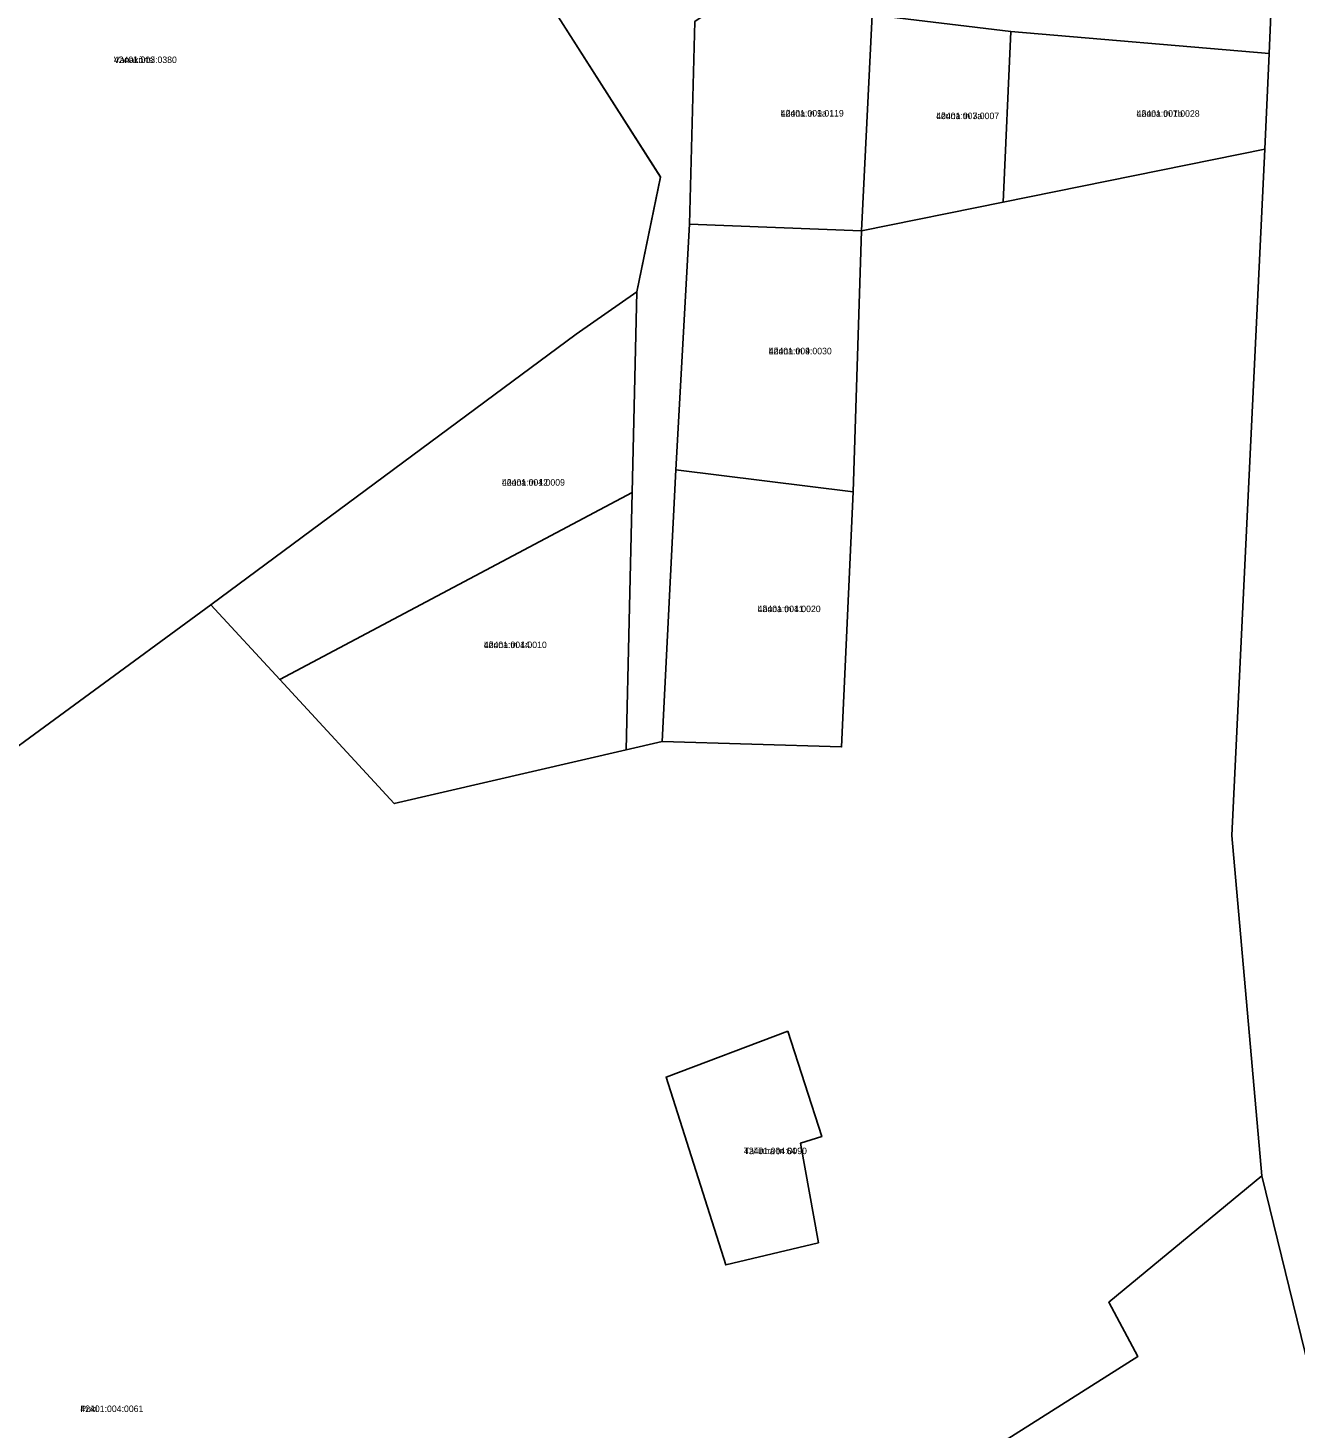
# Model space of a CAD drawing. Extents: x 595979 to 597983, y 6604231 to 6607350.
# Drawn here: x 597176.2 to 597468, y 6604839.1 to 6605161.4 of the extents above; entities that cross this region are included whole.
import ezdxf

# ---------------------------------------------------------------- set-up
doc = ezdxf.new("R2010")
doc.units = 0
for name, color, linetype in [('L_AADRESS', 7, 'Continuous'), ('PIIR', 7, 'Continuous'), ('TUNNUS', 7, 'Continuous')]:
    doc.layers.add(name, color=color, linetype=linetype)

msp = doc.modelspace()

# ---------------------------------------------------------------- linework, layer by layer
at = {"layer": 'PIIR'}
for points in [[(597491.74, 6604767.94), (597460.13, 6604897.15), (597453.23, 6604975.44), (597460.84, 6605133.45), (597461.82, 6605155.54), (597462.44, 6605169.92), (597464.18, 6605199.35), (597465.36, 6605215.89), (597466.32, 6605232.67), (597467.99, 6605256.4), (597471.01, 6605303.31), (597471.58, 6605313.69), (597473.22, 6605343.42), (597478.52, 6605366.25), (597479.63, 6605378.15), (597480.24, 6605385.69), (597483.61, 6605418.8), (597487.25, 6605511.01)], [(597462.44, 6605169.92), (597461.82, 6605155.54), (597402.38, 6605160.58), (597370.47, 6605164.38)], [(597329.67, 6605162.91), (597328.4, 6605116.18), (597325.31, 6605059.68), (597322.16, 6604997.14), (597313.87, 6604995.22), (597315.2, 6605054.43), (597316.32, 6605100.66), (597321.77, 6605127.05), (597299.38, 6605162.18)]]:
    msp.add_lwpolyline(points, dxfattribs=at)
for points in [[(597070.11, 6605259.35), (597211.99, 6605298.86), (597260.5, 6605224.72), (597285.2, 6605184.34), (597299.38, 6605162.18), (597321.75, 6605127.1), (597316.32, 6605100.66), (597302.35, 6605090.93), (597218.27, 6605028.59), (597130.93, 6604964.61), (597074.78, 6605236.74)], [(597370.47, 6605164.38), (597368.02, 6605114.71), (597328.4, 6605116.18), (597329.67, 6605162.91), (597337.07, 6605167.91)], [(597368.02, 6605114.71), (597370.47, 6605164.38), (597402.38, 6605160.58), (597400.65, 6605121.3)], [(597402.38, 6605160.58), (597461.82, 6605155.54), (597460.84, 6605133.45), (597400.65, 6605121.3)], [(596935.31, 6604652.73), (596884.36, 6604783.54), (597130.93, 6604964.61), (597218.27, 6605028.59), (597234.13, 6605011.38), (597260.45, 6604982.81), (597313.87, 6604995.22), (597322.16, 6604997.15), (597363.45, 6604995.88), (597366.07, 6605054.58), (597368.02, 6605114.71), (597400.65, 6605121.3), (597460.84, 6605133.45), (597453.23, 6604975.44), (597460.13, 6604897.15), (597424.92, 6604868.01), (597431.6, 6604855.49), (597190.21, 6604702.64), (596975.34, 6604552.03)], [(597368.02, 6605114.71), (597366.07, 6605054.58), (597325.31, 6605059.68), (597328.4, 6605116.18)], [(597234.13, 6605011.38), (597218.27, 6605028.59), (597302.35, 6605090.93), (597316.32, 6605100.66), (597315.2, 6605054.43)], [(597363.45, 6604995.88), (597322.16, 6604997.14), (597325.31, 6605059.68), (597366.07, 6605054.58)], [(597260.45, 6604982.81), (597234.13, 6605011.38), (597315.2, 6605054.43), (597313.87, 6604995.22)], [(597351.09, 6604930.41), (597323.03, 6604919.87), (597336.78, 6604876.62), (597358.09, 6604881.72), (597354.01, 6604904.66), (597358.86, 6604906.17)], [(597351.09, 6604930.41), (597358.86, 6604906.17), (597354.01, 6604904.66), (597358.09, 6604881.72), (597336.78, 6604876.62), (597323.03, 6604919.87)], [(597036.92, 6604395.59), (596986.98, 6604522.29), (596975.34, 6604552.03), (597190.21, 6604702.64), (597431.6, 6604855.49), (597424.92, 6604868.01), (597460.13, 6604897.15), (597491.74, 6604767.94), (597361.63, 6604743.85), (597410.5, 6604564.41), (597223.16, 6604412.75), (597062.73, 6604330.32)]]:
    msp.add_lwpolyline(points, close=True, dxfattribs=at)

# ---------------------------------------------------------------- texts
at = {"layer": 'L_AADRESS'}
for s, p in [('Vanakõrtsi', (597195.93, 6605153.31)), ('Lõuna tn 9a', (597349.43, 6605141)), ('Lõuna tn 7a', (597385.2, 6605140.4)), ('Lõuna tn 7b', (597431.34, 6605140.94)), ('Lõuna tn 9', (597346.67, 6605086.26)), ('Lõuna tn 12', (597285.25, 6605056.02)), ('Lõuna tn 11', (597344.11, 6605026.9)), ('Lõuna tn 14', (597281.08, 6605018.62)), ('Tallinna tn 64', (597340.95, 6604902.11)), ('Puki', (597188.22, 6604842.74))]:
    msp.add_text(s, height=1.5, dxfattribs=at).set_placement(p)
at = {"layer": 'TUNNUS'}
for s, p in [('42401:003:0380', (597195.93, 6605153.31)), ('42401:001:0119', (597349.43, 6605141)), ('42401:003:0007', (597385.2, 6605140.4)), ('42401:001:0028', (597431.34, 6605140.94)), ('42401:004:0030', (597346.67, 6605086.26)), ('42401:004:0009', (597285.25, 6605056.02)), ('42401:004:0020', (597344.11, 6605026.9)), ('42401:004:0010', (597281.08, 6605018.62)), ('42401:004:0090', (597340.95, 6604902.11)), ('42401:004:0061', (597188.22, 6604842.74))]:
    msp.add_text(s, height=1.5, dxfattribs=at).set_placement(p)

doc.saveas('drawing.dxf')
